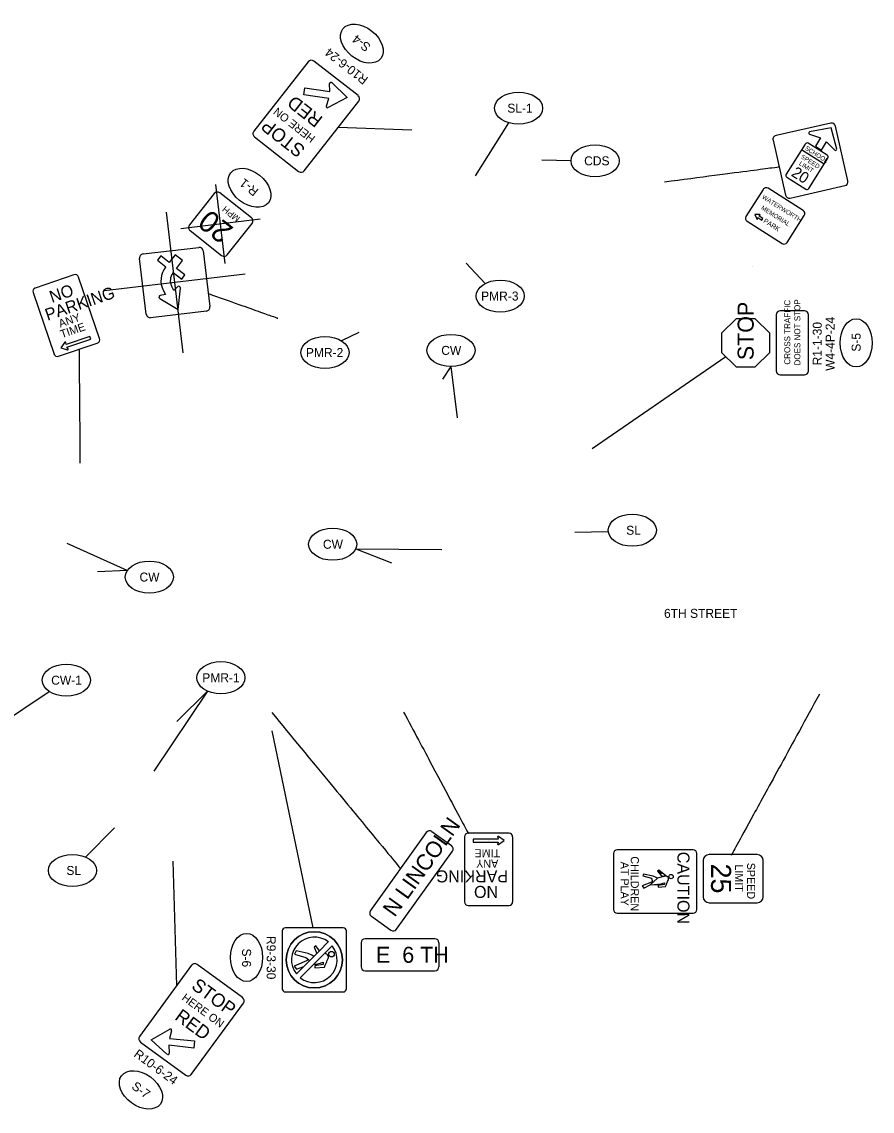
# Model space of a CAD drawing. Extents: x 108269 to 109415, y 548506 to 548874.
# Drawn here: x 108341.9 to 108474.5, y 548673.6 to 548843.5 of the extents above; entities that cross this region are included whole.
import ezdxf

# ---------------------------------------------------------------- set-up
doc = ezdxf.new("R2010")
doc.units = 0
for name, color, linetype in [('Default', 7, 'Continuous'), ('PM_P_Removal', 7, 'Continuous'), ('SH_Data', 7, 'Continuous'), ('SH_Text', 7, 'Continuous'), ('SN_P_Signs', 7, 'Continuous'), ('SN_P_Text', 7, 'Continuous'), ('SN_X_Public', 7, 'Continuous')]:
    doc.layers.add(name, color=color, linetype=linetype)

msp = doc.modelspace()

# ---------------------------------------------------------------- linework, layer by layer
at = {"layer": 'Default'}
for p, q in [((108412.65, 548819.43), (108417.89, 548827.71)), ((108427.57, 548821.79), (108423, 548821.88)), ((108411.24, 548805.83), (108414.2, 548802.67)), ((108394.47, 548795.05), (108391.8, 548793.71)), ((108408.85, 548789.74), (108407.51, 548787.74)), ((108408.85, 548789.74), (108409.82, 548781.74)), ((108428.15, 548763.89), (108433.37, 548764.02)), ((108358.39, 548757.92), (108349, 548762.15)), ((108394.01, 548761.32), (108407.44, 548761.23)), ((108394.01, 548761.32), (108399.6, 548759.13)), ((108358.39, 548757.92), (108353.74, 548757.74)), ((108335.9, 548732.19), (108346.23, 548739.07)), ((108370.9, 548739.14), (108362.54, 548726.63)), ((108366.11, 548734.37), (108370.9, 548739.14)), ((108351.9, 548713.27), (108356.39, 548717.83))]:
    msp.add_line(p, q, dxfattribs=at)
for centre, major_axis in [((108394.96, 548840.06), (-2.95, 2.31)), ((108419.39, 548830), (3.75, 0)), ((108377.45, 548817.59), (-2.94, 2.33)), ((108416.52, 548800.71), (3.75, 0)), ((108472.01, 548793.41), (0, 3.75)), ((108389.21, 548791.91), (3.75, 0)), ((108372.98, 548741.22), (3.75, 0)), ((108348.89, 548740.83), (3.75, 0)), ((108376.99, 548697.61), (0, -3.75)), ((108360.52, 548676.97), (3.03, -2.21))]:
    msp.add_ellipse(centre, major_axis=major_axis, ratio=0.666667, dxfattribs=at)
at = {"layer": 'PM_P_Removal'}
for centre in [(108431.32, 548821.79), (108408.85, 548792.24), (108437.11, 548764.2), (108390.41, 548762.02), (108361.83, 548756.91), (108349.85, 548711.17)]:
    msp.add_ellipse(centre, major_axis=(3.75, 0), ratio=0.666667, dxfattribs=at)
at = {"layer": 'SH_Data'}
for points in [[(108442.13, 548818.52), (108459.98, 548820.86), (108459.98, 548820.86), (108459.98, 548820.86)], [(108371.03, 548801.09), (108381.84, 548797.26), (108381.84, 548797.26), (108381.84, 548797.26)], [(108351.07, 548774.65), (108350.93, 548792.43), (108350.93, 548792.43), (108350.93, 548792.43)], [(108466.28, 548738.65), (108452.6, 548713.64), (108452.6, 548713.64), (108452.6, 548713.64)], [(108380.9, 548735.81), (108400.98, 548711.47), (108400.98, 548711.47), (108400.98, 548711.47)], [(108401.47, 548735.87), (108411.53, 548716.98), (108411.53, 548716.98), (108411.53, 548716.98)]]:
    msp.add_open_spline(points, degree=2, dxfattribs=at)
at = {"layer": 'SH_Text'}
for p, q in [((108402.77, 548826.55), (108391.27, 548827)), ((108430.88, 548776.94), (108451.67, 548791.28)), ((108387.36, 548702.24), (108381, 548732.96)), ((108366.09, 548693.21), (108365.52, 548712.62))]:
    msp.add_line(p, q, dxfattribs=at)
at = {"layer": 'SN_P_Signs'}
for p, q in [((108386.6, 548837.24), (108378.11, 548826.42)), ((108394.36, 548831.95), (108387.47, 548837.35)), ((108389.95, 548832.59), (108389.92, 548833.83)), ((108390.28, 548833.98), (108392.65, 548831.66)), ((108385.93, 548832.06), (108386.09, 548833.15)), ((108389.79, 548831.51), (108385.93, 548832.06)), ((108386.09, 548833.15), (108389.95, 548832.59)), ((108385.98, 548820.25), (108394.46, 548831.07)), ((108389.43, 548830.34), (108389.79, 548831.51)), ((108392.65, 548831.66), (108389.72, 548830.09)), ((108378.22, 548825.54), (108385.1, 548820.14)), ((108385.97, 548820.25), (108385.98, 548820.25)), ((108453.28, 548797.16), (108451.03, 548794.91)), ((108456.28, 548797.16), (108453.28, 548797.16)), ((108458.53, 548794.91), (108456.28, 548797.16)), ((108451.03, 548794.91), (108451.03, 548791.91)), ((108458.53, 548791.91), (108458.53, 548794.91)), ((108451.03, 548791.91), (108453.28, 548789.66)), ((108456.28, 548789.66), (108458.53, 548791.91)), ((108453.28, 548789.66), (108456.28, 548789.66)), ((108438.88, 548710.61), (108438.77, 548710.34)), ((108438.77, 548710.34), (108440.12, 548709.95)), ((108440.34, 548710.29), (108438.88, 548710.61)), ((108440.34, 548710.29), (108438.88, 548710.61)), ((108441.03, 548709.95), (108439.92, 548708.91)), ((108439.92, 548708.91), (108441.01, 548709.93)), ((108440.12, 548709.95), (108440.28, 548709.41)), ((108440.84, 548710.05), (108440.34, 548710.29)), ((108440.84, 548710.05), (108440.34, 548710.29)), ((108441.03, 548709.95), (108440.84, 548710.05)), ((108441.03, 548709.95), (108440.84, 548710.05)), ((108441.01, 548709.93), (108441.03, 548709.95)), ((108442.32, 548710.32), (108441.03, 548709.95)), ((108441.26, 548711.22), (108441.04, 548711.06)), ((108441.04, 548711.06), (108441.56, 548710.42)), ((108441.71, 548710.63), (108441.26, 548711.22)), ((108442.32, 548710.32), (108441.26, 548711.22)), ((108441.56, 548710.42), (108442, 548710.21)), ((108440.28, 548709.41), (108438.65, 548708.77)), ((108438.65, 548708.77), (108438.91, 548708.43)), ((108438.65, 548708.77), (108438.91, 548708.43)), ((108438.91, 548708.43), (108439.92, 548708.91)), ((108441.14, 548708.82), (108441.12, 548708.57)), ((108441.14, 548708.82), (108441.12, 548708.57)), ((108441.12, 548708.57), (108442.28, 548708.66)), ((108441.12, 548708.57), (108442.28, 548708.66)), ((108442.12, 548708.96), (108441.14, 548708.82)), ((108442.12, 548708.96), (108441.14, 548708.82)), ((108442.13, 548709.24), (108442.12, 548708.96)), ((108442.13, 548709.24), (108442.12, 548708.96)), ((108442.28, 548708.66), (108442.28, 548708.66)), ((108442.28, 548708.66), (108442.28, 548708.66)), ((108384.71, 548698.63), (108384.45, 548698.12)), ((108384.71, 548698.63), (108384.45, 548698.12)), ((108384.45, 548698.12), (108386.22, 548697.6)), ((108384.45, 548698.12), (108386.22, 548697.6)), ((108386.59, 548698.22), (108384.71, 548698.63)), ((108386.59, 548698.22), (108384.71, 548698.63)), ((108390.33, 548699.43), (108385.35, 548694.46)), ((108387.24, 548697.92), (108386.59, 548698.22)), ((108387.24, 548697.92), (108386.59, 548698.22)), ((108387.49, 548697.78), (108387.24, 548697.92)), ((108387.49, 548697.78), (108387.24, 548697.92)), ((108387.79, 548699.43), (108387.5, 548699.23)), ((108387.79, 548699.43), (108387.5, 548699.23)), ((108387.5, 548699.23), (108387.95, 548698.24)), ((108387.5, 548699.23), (108387.95, 548698.24)), ((108389.11, 548698.21), (108387.5, 548696.6)), ((108388.37, 548698.66), (108387.79, 548699.43)), ((108388.37, 548698.66), (108387.79, 548699.43)), ((108387.95, 548698.24), (108388.04, 548698.33)), ((108389.16, 548698.26), (108389.11, 548698.21)), ((108368.42, 548696.39), (108360.3, 548685.29)), ((108368.42, 548696.39), (108368.42, 548696.39)), ((108376.35, 548691.36), (108369.29, 548696.53)), ((108386.67, 548697.24), (108384.41, 548696.26)), ((108386.67, 548697.24), (108384.41, 548696.26)), ((108384.41, 548696.26), (108384.75, 548695.81)), ((108384.41, 548696.26), (108384.75, 548695.81)), ((108384.75, 548695.81), (108385.92, 548696.21)), ((108384.75, 548695.81), (108385.92, 548696.21)), ((108385.92, 548696.21), (108387.46, 548697.75)), ((108386.22, 548697.6), (108386.67, 548697.24)), ((108386.22, 548697.6), (108386.67, 548697.24)), ((108387.46, 548697.75), (108387.49, 548697.78)), ((108387.64, 548696.31), (108387.61, 548695.99)), ((108387.64, 548696.31), (108387.61, 548695.99)), ((108388.91, 548696.5), (108387.64, 548696.31)), ((108388.91, 548696.5), (108387.64, 548696.31)), ((108388.92, 548696.86), (108388.91, 548696.5)), ((108388.92, 548696.86), (108388.91, 548696.5)), ((108387.61, 548695.99), (108389.11, 548696.11)), ((108387.61, 548695.99), (108389.11, 548696.11)), ((108389.11, 548696.11), (108389.11, 548696.12)), ((108389.11, 548696.11), (108389.11, 548696.12)), ((108368.37, 548679.39), (108376.49, 548690.48)), ((108362.13, 548684.77), (108365.01, 548686.43)), ((108365.31, 548686.19), (108364.99, 548685)), ((108360.43, 548684.42), (108367.5, 548679.25)), ((108364.58, 548682.53), (108362.13, 548684.77)), ((108364.99, 548685), (108368.86, 548684.59)), ((108368.86, 548684.59), (108368.74, 548683.49)), ((108368.74, 548683.49), (108364.86, 548683.92)), ((108364.86, 548683.92), (108364.93, 548682.69))]:
    msp.add_line(p, q, dxfattribs=at)
for points in [[(108463.93, 548798.41), (108460.18, 548798.41)], [(108459.56, 548797.79), (108459.56, 548789.04)], [(108464.56, 548789.04), (108464.56, 548797.79)], [(108460.18, 548788.41), (108463.93, 548788.41)], [(108441.03, 548709.95), (108441.03, 548709.95)], [(108442, 548710.21), (108442.32, 548710.32), (108442.32, 548710.32)], [(108382.54, 548701.74), (108382.54, 548692.74)], [(108392.04, 548702.24), (108383.04, 548702.24)], [(108392.54, 548692.74), (108392.54, 548701.74)], [(108389.73, 548700.03), (108388.38, 548698.67), (108388.04, 548698.32), (108388.04, 548698.33)], [(108388.04, 548698.33), (108387.46, 548697.75), (108385.61, 548695.9), (108384.76, 548695.05)], [(108385.35, 548694.45), (108387.33, 548696.43), (108387.33, 548696.43), (108387.33, 548696.43), (108389.11, 548698.21), (108389.11, 548698.21)], [(108388.04, 548698.33), (108388.37, 548698.66), (108388.37, 548698.66)], [(108389.11, 548698.21), (108390.33, 548699.43)], [(108389.11, 548698.21), (108389.11, 548698.21)], [(108383.04, 548692.24), (108392.04, 548692.24)]]:
    msp.add_lwpolyline(points, dxfattribs=at)
for centre, radius in [((108443.15, 548710.22), 0.334), ((108387.54, 548697.24), 4.38), ((108390.23, 548698.13), 0.432)]:
    msp.add_circle(centre, radius, dxfattribs=at)
for centre, radius, start, end in [((108387.08, 548836.85), 0.625, 51.8936, 141.8936), ((108390.13, 548833.83), 0.208, 43.3534, 185.9293), ((108389.62, 548830.27), 0.208, 159.8639, 300.4822), ((108393.97, 548831.45), 0.625, 321.8936, 51.8936), ((108378.6, 548826.04), 0.625, 141.8936, 231.8936), ((108385.48, 548820.64), 0.625, 231.8936, 321.8936), ((108460.18, 548797.79), 0.625, 90, 180), ((108463.93, 548797.79), 0.625, 360, 90), ((108460.18, 548789.04), 0.625, 180, 270), ((108463.93, 548789.04), 0.625, 270, 360), ((108383.04, 548701.74), 0.5, 90, 180), ((108387.54, 548697.24), 4.38, 90, 270), ((108387.54, 548697.24), 4.38, 270, 90), ((108392.04, 548701.74), 0.5, 360, 90), ((108387.54, 548697.24), 3.55, 51.8479, 218.248), ((108387.54, 548697.24), 3.55, 51.8479, 218.248), ((108387.54, 548697.24), 3.55, 231.8191, 38.1713), ((108387.54, 548697.24), 3.55, 231.8191, 38.1713), ((108388.64, 548697.6), 0.768, 52.0752, 52.1283), ((108368.93, 548696.02), 0.625, 53.8015, 143.8015), ((108375.99, 548690.85), 0.625, 323.8015, 53.8015), ((108383.04, 548692.74), 0.5, 180, 270), ((108392.04, 548692.74), 0.5, 270, 360), ((108365.11, 548686.25), 0.208, 341.7718, 122.3901), ((108360.81, 548684.93), 0.625, 143.8015, 233.8015), ((108364.73, 548682.68), 0.208, 225.2613, 7.8372), ((108367.87, 548679.76), 0.625, 233.8015, 323.8015)]:
    msp.add_arc(centre, radius, start, end, dxfattribs=at)
for points in [[(108442.28, 548708.66), (108442.43, 548709), (108442.67, 548709.54), (108442.76, 548709.74), (108442.78, 548709.8), (108442.78, 548709.87), (108442.78, 548710.02), (108442.59, 548710.22), (108442.42, 548710.28), (108442.32, 548710.32)], [(108442.28, 548708.66), (108442.43, 548709), (108442.67, 548709.54), (108442.76, 548709.74), (108442.78, 548709.8), (108442.78, 548709.87), (108442.78, 548710.02), (108442.59, 548710.22), (108442.42, 548710.28), (108442.32, 548710.32)], [(108439.92, 548708.91), (108441.06, 548709.02), (108441.14, 548709), (108441.32, 548709.01), (108441.48, 548709.04), (108441.76, 548709.12), (108441.95, 548709.18), (108442.13, 548709.24)], [(108441.04, 548709.04), (108441.06, 548709.02), (108441.14, 548709), (108441.32, 548709.01), (108441.48, 548709.04), (108441.76, 548709.12), (108441.95, 548709.18), (108442.13, 548709.24)], [(108389.11, 548696.12), (108389.3, 548696.56), (108389.62, 548697.25), (108389.73, 548697.51), (108389.75, 548697.59), (108389.75, 548697.68), (108389.75, 548697.88), (108389.51, 548698.13), (108389.29, 548698.21), (108389.16, 548698.26)], [(108389.11, 548696.12), (108389.3, 548696.56), (108389.62, 548697.25), (108389.73, 548697.51), (108389.75, 548697.59), (108389.75, 548697.68), (108389.75, 548697.88), (108389.51, 548698.13), (108389.29, 548698.21), (108389.16, 548698.26)], [(108387.5, 548696.6), (108387.53, 548696.58), (108387.63, 548696.55), (108387.86, 548696.57), (108388.07, 548696.61), (108388.43, 548696.71), (108388.68, 548696.78), (108388.92, 548696.86)], [(108387.5, 548696.6), (108387.53, 548696.58), (108387.63, 548696.55), (108387.86, 548696.57), (108388.07, 548696.61), (108388.43, 548696.71), (108388.68, 548696.78), (108388.92, 548696.86)]]:
    msp.add_open_spline(points, degree=3, dxfattribs=at)
at = {"layer": 'SN_X_Public'}
for p, q in [((108468.12, 548826.94), (108464.76, 548826.29)), ((108468.97, 548823.63), (108468.12, 548826.94)), ((108464.73, 548825.96), (108466.47, 548825.36)), ((108466.47, 548825.36), (108465.65, 548824.06)), ((108465.65, 548824.06), (108466.58, 548823.47)), ((108466.58, 548823.47), (108467.4, 548824.77)), ((108467.4, 548824.77), (108468.69, 548823.47)), ((108467, 548821.27), (108463.47, 548823.49)), ((108373.66, 548805.77), (108372.2, 548818.12)), ((108377.74, 548812.92), (108372.84, 548816.79)), ((108371.96, 548816.69), (108368.09, 548811.79)), ((108367.09, 548791.85), (108364.49, 548813.79)), ((108456.95, 548813.44), (108456.23, 548813.4)), ((108456.23, 548813.4), (108456.51, 548812.74)), ((108456.84, 548813.2), (108457, 548813.33)), ((108379.11, 548812.68), (108366.76, 548811.21)), ((108373.97, 548807.14), (108377.85, 548812.04)), ((108456.63, 548812.75), (108456.68, 548812.94)), ((108456.68, 548812.94), (108457.29, 548812.55)), ((108456.68, 548812.94), (108456.68, 548812.94)), ((108457.29, 548812.55), (108457.46, 548812.81)), ((108368.19, 548810.91), (108373.09, 548807.03)), ((108363.62, 548806.97), (108363.1, 548806.31)), ((108364.93, 548805.93), (108363.62, 548806.97)), ((108365.87, 548807.13), (108364.93, 548805.93)), ((108367.02, 548806.23), (108365.87, 548807.13)), ((108363.1, 548806.31), (108364.41, 548805.28)), ((108364.41, 548805.28), (108364.35, 548805.2)), ((108366.07, 548805.03), (108367.02, 548806.23)), ((108367.38, 548804), (108366.07, 548805.03)), ((108455.83, 548805.37), (108455.83, 548805.37)), ((108376.76, 548804.12), (108354.82, 548801.52)), ((108365.49, 548804.29), (108365.56, 548804.38)), ((108365.56, 548804.38), (108366.87, 548803.34)), ((108366.87, 548803.34), (108367.38, 548804)), ((108364, 548801.62), (108364.34, 548800.95)), ((108365.64, 548801.6), (108365.3, 548802.28)), ((108366.27, 548802.19), (108365.64, 548801.6)), ((108366.34, 548798.63), (108366.67, 548801.95)), ((108363.46, 548800.33), (108366.34, 548798.63)), ((108363.46, 548800.33), (108363.46, 548800.33)), ((108364.34, 548800.95), (108363.51, 548800.8)), ((108348.67, 548793.51), (108348.03, 548792.64)), ((108348.84, 548793.16), (108348.83, 548793.46)), ((108348.99, 548792.72), (108352.69, 548793.98)), ((108350.32, 548793.42), (108350.32, 548793.42)), ((108352.69, 548793.98), (108352.54, 548794.43)), ((108348.03, 548792.64), (108349.07, 548792.34)), ((108349.17, 548792.48), (108348.99, 548792.72)), ((108348.99, 548792.72), (108348.99, 548792.72)), ((108416.21, 548716.07), (108412.31, 548716.07)), ((108412.31, 548716.07), (108412.31, 548715.6)), ((108414.73, 548715.84), (108414.73, 548715.84)), ((108416.13, 548716.36), (108416.22, 548716.07)), ((108416.22, 548715.6), (108416.13, 548715.32)), ((108416.22, 548716.07), (108416.21, 548716.07)), ((108417.15, 548715.84), (108416.27, 548716.46)), ((108416.27, 548715.22), (108417.15, 548715.84)), ((108437.09, 548709.73), (108437.09, 548709.73))]:
    msp.add_line(p, q, dxfattribs=at)
for points in [[(108468.06, 548827.67), (108459.52, 548825.74)], [(108470.73, 548818.67), (108468.8, 548827.2)], [(108459.05, 548824.99), (108460.98, 548816.46)], [(108464.06, 548824.41), (108461.09, 548819.71)], [(108467.47, 548822.67), (108464.54, 548824.52)], [(108464.62, 548817.49), (108467.58, 548822.19)], [(108461.2, 548819.23), (108464.14, 548817.38)], [(108457.49, 548817.34), (108454.83, 548813.13)], [(108463.74, 548814.07), (108458.27, 548817.52)], [(108461.73, 548815.99), (108470.26, 548817.92)], [(108455.01, 548812.36), (108460.48, 548808.9)], [(108457.46, 548812.81), (108456.85, 548813.2)], [(108461.26, 548809.08), (108463.92, 548813.29)], [(108360.86, 548807.27), (108369.55, 548808.3)], [(108361.34, 548797.89), (108360.31, 548806.58)], [(108370.24, 548807.75), (108371.27, 548799.07)], [(108350.08, 548804.02), (108344.05, 548801.96)], [(108354.07, 548794.09), (108350.8, 548803.67)], [(108343.7, 548801.25), (108346.97, 548791.67)], [(108370.72, 548798.37), (108362.03, 548797.34)], [(108347.69, 548791.32), (108353.72, 548793.38)], [(108352.54, 548794.43), (108348.84, 548793.16)], [(108405, 548717.1), (108396.29, 548704.92)], [(108405.87, 548717.24), (108408.92, 548715.06)], [(108417.9, 548716.98), (108411.53, 548716.98)], [(108410.97, 548716.41), (108410.97, 548706.29)], [(108412.31, 548715.6), (108416.21, 548715.6)], [(108418.47, 548706.29), (108418.47, 548716.41)], [(108400.36, 548702.01), (108409.07, 548714.19)], [(108434.18, 548713.81), (108434.18, 548705.08)], [(108446.61, 548714.37), (108434.74, 548714.37)], [(108447.18, 548705.08), (108447.18, 548713.81)], [(108456.58, 548713.64), (108449.08, 548713.64)], [(108448.14, 548712.7), (108448.14, 548707.08)], [(108457.51, 548707.08), (108457.51, 548712.7)], [(108411.53, 548705.73), (108417.9, 548705.73)], [(108449.08, 548706.14), (108456.58, 548706.14)], [(108396.44, 548704.04), (108399.49, 548701.86)], [(108434.74, 548704.52), (108446.61, 548704.52)], [(108394.85, 548699.91), (108394.85, 548696.16)], [(108406.35, 548700.53), (108395.47, 548700.53)], [(108406.98, 548699.91), (108406.98, 548696.16)], [(108395.47, 548695.53), (108406.35, 548695.53)]]:
    msp.add_lwpolyline(points, dxfattribs=at)
for centre, radius, start, end in [((108468.19, 548827.06), 0.625, 12.7503, 102.7503), ((108459.66, 548825.13), 0.625, 102.7503, 192.7503), ((108464.79, 548826.12), 0.17, 101.0146, 250.9909), ((108464.35, 548824.23), 0.347, 57.7503, 147.7503), ((108468.81, 548823.59), 0.17, 224.5098, 14.486), ((108467.29, 548822.37), 0.347, 327.7503, 57.7503), ((108461.39, 548819.53), 0.347, 147.7503, 237.7503), ((108470.12, 548818.53), 0.625, 282.7503, 12.7503), ((108372.45, 548816.3), 0.625, 51.6702, 141.6702), ((108457.97, 548817.04), 0.562, 57.7503, 147.7503), ((108464.32, 548817.67), 0.347, 237.7503, 327.7503), ((108461.59, 548816.6), 0.625, 192.7503, 282.7503), ((108456.96, 548813.38), 0.061, 310.1125, 92.8296), ((108463.44, 548813.59), 0.562, 327.7503, 57.7503), ((108368.58, 548811.4), 0.625, 141.6702, 231.6702), ((108377.36, 548812.43), 0.625, 321.6702, 51.6702), ((108455.31, 548812.83), 0.562, 147.7503, 237.7503), ((108456.57, 548812.76), 0.061, 202.6711, 345.3881), ((108369.62, 548807.68), 0.625, 6.7528, 96.7528), ((108460.78, 548809.38), 0.562, 237.7503, 327.7503), ((108360.93, 548806.65), 0.625, 96.7528, 186.7528), ((108373.48, 548807.52), 0.625, 231.6702, 321.6702), ((108366.97, 548803.13), 3.33, 141.7528, 207.0089), ((108350.26, 548803.49), 0.562, 18.859, 108.859), ((108366.97, 548803.13), 1.87, 141.7528, 207.0089), ((108344.23, 548801.43), 0.562, 108.859, 198.859), ((108366.42, 548801.98), 0.256, 353.7417, 125.9679), ((108363.59, 548800.56), 0.256, 107.5376, 239.7638), ((108370.65, 548798.99), 0.625, 276.7528, 6.7528), ((108361.96, 548797.96), 0.625, 186.7528, 276.7528), ((108348.74, 548793.46), 0.0912, 1.2212, 143.9382), ((108353.54, 548793.91), 0.562, 288.859, 18.859), ((108347.5, 548791.85), 0.562, 198.859, 288.859), ((108349.09, 548792.42), 0.0912, 253.7797, 36.4968), ((108405.51, 548716.73), 0.625, 54.4426, 144.4426), ((108411.53, 548716.41), 0.562, 90, 180), ((108417.9, 548716.41), 0.562, 360, 90), ((108408.56, 548714.55), 0.625, 324.4426, 54.4426), ((108416.21, 548716.38), 0.0912, 54.9207, 197.6378), ((108416.21, 548715.29), 0.0912, 162.3622, 305.0792), ((108434.74, 548713.81), 0.562, 90, 180), ((108446.61, 548713.81), 0.562, 0, 90), ((108449.08, 548712.7), 0.938, 90, 180), ((108456.58, 548712.7), 0.938, 360, 90), ((108449.08, 548707.08), 0.938, 180, 270), ((108456.58, 548707.08), 0.938, 270, 360), ((108396.8, 548704.55), 0.625, 144.4426, 234.4426), ((108411.53, 548706.29), 0.562, 180, 270), ((108417.9, 548706.29), 0.562, 270, 360), ((108434.74, 548705.08), 0.562, 180, 270), ((108446.61, 548705.08), 0.562, 270, 360), ((108399.85, 548702.37), 0.625, 234.4426, 324.4426), ((108395.47, 548699.91), 0.625, 90, 180), ((108406.35, 548699.91), 0.625, 0, 90), ((108395.47, 548696.16), 0.625, 180, 270), ((108406.35, 548696.16), 0.625, 270, 0)]:
    msp.add_arc(centre, radius, start, end, dxfattribs=at)

# ---------------------------------------------------------------- texts
at = {"layer": 'Default'}
for s, rotation, p in [('S-4', 141.8936, (108396.46, 548839.78)), ('R-1', 141.6702, (108378.98, 548817.27)), ('S-5', 90, (108472.71, 548792.04)), ('S-6', 270, (108376.29, 548699.01)), ('S-7', 323.8015, (108358.95, 548677.25))]:
    msp.add_text(s, height=1.4, rotation=rotation, dxfattribs=at).set_placement(p)
for s, p in [('SL-1', (108417.63, 548829.3)), ('PMR-3', (108413.55, 548800.01)), ('PMR-2', (108386.24, 548791.21)), ('CW-1', (108346.53, 548740.13)), ('PMR-1', (108370.08, 548740.52))]:
    msp.add_text(s, height=1.4, dxfattribs=at).set_placement(p)
at = {"layer": 'PM_P_Removal'}
for s, p in [('CDS', (108429.61, 548821.09)), ('CW', (108407.33, 548791.54)), ('SL', (108436.16, 548763.5)), ('CW', (108388.89, 548761.32)), ('CW', (108360.3, 548756.21)), ('SL', (108348.9, 548710.47))]:
    msp.add_text(s, height=1.4, dxfattribs=at).set_placement(p)
at = {"layer": 'SN_P_Signs'}
for s, height, rotation, p in [('RED', 2.075, 141.8936, (108389.02, 548828.49)), ('HERE ON', 1.25, 141.8936, (108387.8, 548825.49)), ('STOP', 2.075, 141.8936, (108386.28, 548823.78)), ('CROSS TRAFFIC', 0.9375, 90, (108461.74, 548790.02)), ('DOES NOT STOP', 0.9375, 90, (108463.31, 548789.89)), ('STOP', 2.5, 89.9553, (108456.03, 548790.72)), ('STOP', 2.075, 323.8015, (108368.24, 548692.85)), ('HERE ON', 1.25, 323.8015, (108366.77, 548691.09)), ('RED', 2.075, 323.8015, (108365.65, 548688.05))]:
    msp.add_text(s, height=height, rotation=rotation, dxfattribs=at).set_placement(p)
at = {"layer": 'SN_P_Text'}
for s, rotation, p in [('R10-6-24', 141.8936, (108396.06, 548834.68)), ('R1-1-30', 90, (108466.64, 548789.91)), ('W4-4P-24', 90, (108468.65, 548789.05)), ('R9-3-30', 270, (108380.13, 548700.96)), ('R10-6-24', 323.8015, (108359.3, 548682.28))]:
    msp.add_text(s, height=1.4, rotation=rotation, dxfattribs=at).set_placement(p)
msp.add_text('6TH STREET', height=1.4, dxfattribs=at).set_placement((108442.06, 548750.55))
at = {"layer": 'SN_X_Public'}
for s, height, rotation, p in [('SCHOOL', 0.694, 327.7503, (108463.96, 548823.57)), ('SPEED', 0.694, 327.7503, (108463.32, 548822.25)), ('20', 1.736, 327.7503, (108461.77, 548819.53)), ('LIMIT', 0.694, 327.7503, (108463.03, 548821.2)), ('WATERWORTH', 0.694, 327.7503, (108457.26, 548815.96)), ('20', 3.333, 141.6702, (108375.1, 548811.29)), ('MPH', 1.021, 141.6702, (108376.09, 548812.95)), ('MEMORIAL', 0.694, 327.7503, (108457.12, 548814.27)), ('PARK', 0.75, 327.7503, (108457.47, 548812.23)), ('PARKING', 1.875, 18.859, (108345.96, 548796.84)), ('NO', 1.875, 18.859, (108346.64, 548799.63)), ('ANY', 1.25, 18.859, (108347.94, 548795.78)), ('TIME', 1.25, 18.859, (108348.19, 548794.13)), ('N LINCOLN', 2.5, 54.4426, (108400.08, 548703.77)), ('TIME', 1.25, 180, (108416.51, 548714.48)), ('CHILDREN', 1.25, 270, (108436.88, 548713.38)), ('CAUTION', 1.875, 270, (108444.15, 548714.09)), ('ANY', 1.25, 180, (108416.22, 548712.84)), ('AT PLAY', 1.25, 270, (108435.31, 548712.53)), ('25', 3.125, 270, (108449.39, 548712.24)), ('LIMIT', 1.25, 270, (108453.14, 548712.12)), ('SPEED', 1.25, 270, (108455.01, 548712.37)), ('PARKING', 1.875, 180, (108417.75, 548711.19)), ('NO', 1.875, 180, (108416.2, 548708.77))]:
    msp.add_text(s, height=height, rotation=rotation, dxfattribs=at).set_placement(p)
msp.add_text('E  6 TH', height=2.5, dxfattribs=at).set_placement((108397.17, 548696.78))

doc.saveas('drawing.dxf')
